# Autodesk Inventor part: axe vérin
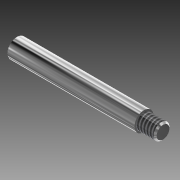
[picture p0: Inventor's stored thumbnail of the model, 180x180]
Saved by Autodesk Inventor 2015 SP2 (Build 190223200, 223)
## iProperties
Created: 2015-08
Part Number: axe vérin
Material: Générique
Document SubType Name: Modeling
Designer: Dominique
Density: 1 g/cm^3
Appearance: Chrome - Poli
Author: Dominique
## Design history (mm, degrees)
sketch "Esquisse1"
  geometry: L1 (0, 0)-(40, 0); L2 (40, 0)-(40, 3); L3 (40, 3)-(0, 3); L4 (0, 3)-(0, 0); L5 (40, 0)-(46, 0); L6 (46, 0)-(46, 2.5); L7 (46, 2.5)-(40, 2.5); L8 (40, 2.5)-(40, 0)
  constraints: 16 end point, 4 parallel, 2 horizontal, 2 perpendicular
  dimensions: "d0" = 40 distance of L3.end L2.end; "d1" = 3 distance of L2.end L1.end; "d2" = 6 distance of L7.end L6.end; "d3" = 2.5 distance of L6.end L5.end
revolve "Révolution1" sketch "Esquisse1" stored, may be unused: angle "d4" = 90 deg
chamfer "Chanfrein1" distance "d5" = 0.5; stored, may be unused: second distance "d6" = 2, angle "d7" = 45 deg
feature "Filetage1" dims "d8" = 10, "d9" = 0
node "Solide1"
